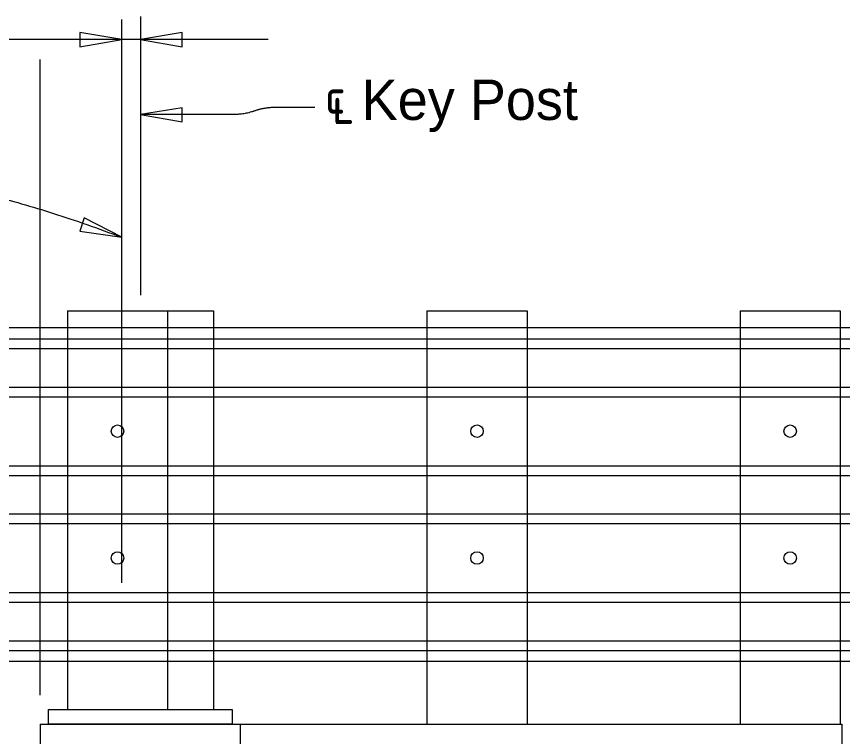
# Model space of a CAD drawing. Extents: x 21526.6 to 21598.7, y 56118.9 to 56155.9.
# Drawn here: x 21535.614 to 21539.735, y 56135.149 to 56138.742 of the extents above; entities that cross this region are included whole.
import ezdxf

# ---------------------------------------------------------------- set-up
doc = ezdxf.new("R2010")
doc.units = 0
for name, color, linetype in [('AdhocPoint_dp', 7, 'Continuous'), ('Border', 7, 'Continuous'), ('Patterning', 7, 'Continuous'), ('PlotBorder_dp', 7, 'Continuous'), ('SheetBorder_dp', 7, 'Continuous'), ('SubStrConc', 7, 'Continuous')]:
    doc.layers.add(name, color=color, linetype=linetype)

msp = doc.modelspace()

# ---------------------------------------------------------------- linework, layer by layer
at = {"layer": 'AdhocPoint_dp'}
for q in [(21535.7321, 56132.6054), (21536.7321, 56135.2101)]:
    msp.add_line((21535.7321, 56135.2101), q, dxfattribs=at)
at = {"layer": 'Patterning'}
for p, q in [((21536.2322, 56138.7421), (21536.2322, 56137.3509)), ((21536.1385, 56135.9162), (21536.1385, 56138.7274)), ((21535.8675, 56137.2726), (21536.5967, 56137.2726)), ((21535.8675, 56137.2726), (21535.8675, 56135.283)), ((21536.3675, 56137.2726), (21536.3675, 56135.283)), ((21537.6617, 56137.2725), (21537.6617, 56135.21)), ((21537.6617, 56137.2725), (21538.1617, 56137.2725)), ((21538.1617, 56137.2725), (21538.1617, 56135.21)), ((21539.2242, 56137.2725), (21539.2242, 56135.21)), ((21539.2242, 56137.2725), (21539.7242, 56137.2725)), ((21539.7242, 56137.2725), (21539.7242, 56135.21))]:
    msp.add_line(p, q, dxfattribs=at)
for centre in [(21536.1175, 56136.6725), (21536.1175, 56136.0393)]:
    msp.add_circle(centre, 0.0312, dxfattribs=at)
at = {"layer": 'PlotBorder_dp'}
for p, q in [((21536.8702, 56138.6267), (21533.9069, 56138.6267)), ((21535.7322, 56135.3555), (21535.7322, 56138.5276))]:
    msp.add_line(p, q, dxfattribs=at)
for points in [[(21536.1385, 56138.6267), (21535.9302, 56138.662), (21535.9302, 56138.5914)], [(21536.2322, 56138.6267), (21536.4405, 56138.5914), (21536.4405, 56138.662)], [(21536.2321, 56138.2534), (21536.44, 56138.2159), (21536.4408, 56138.2864)], [(21536.1385, 56137.6408), (21535.9508, 56137.7376), (21535.9294, 56137.6704)]]:
    msp.add_lwpolyline(points, close=True, dxfattribs=at)
for points in [[(21537.1016, 56138.2883), (21536.9673, 56138.2883), (21536.8507, 56138.2883), (21536.7517, 56138.253), (21536.6457, 56138.253), (21536.2321, 56138.2534)], [(21534.0219, 56137.913), (21534.2745, 56137.9191), (21535.2881, 56137.9608), (21536.1385, 56137.6408)]]:
    msp.add_open_spline(points, degree=2, dxfattribs=at)
at = {"layer": 'SheetBorder_dp'}
for p, q in [((21536.0134, 56137.2726), (21536.0967, 56137.2726)), ((21536.5967, 56137.2726), (21536.5967, 56135.283)), ((21541.6829, 56137.1892), (21534.1592, 56137.1892)), ((21534.1592, 56137.1336), (21541.6829, 56137.1336)), ((21534.1592, 56137.0854), (21541.6829, 56137.0854)), ((21534.1592, 56136.8926), (21541.6829, 56136.8926)), ((21534.1592, 56136.8444), (21541.6829, 56136.8444)), ((21534.1592, 56136.5004), (21541.6829, 56136.5004)), ((21534.1592, 56136.4522), (21541.6829, 56136.4522)), ((21534.1592, 56136.2594), (21541.6829, 56136.2594)), ((21534.1592, 56136.2112), (21541.6829, 56136.2112)), ((21534.1592, 56135.8673), (21541.6829, 56135.8673)), ((21534.1592, 56135.8191), (21541.6829, 56135.8191)), ((21534.1592, 56135.6262), (21541.6829, 56135.6262)), ((21534.1592, 56135.578), (21541.6829, 56135.578)), ((21541.6829, 56135.5225), (21534.1592, 56135.5225))]:
    msp.add_line(p, q, dxfattribs=at)
msp.add_lwpolyline([(21535.7738, 56135.2101), (21535.7738, 56135.283), (21536.6905, 56135.283), (21536.6905, 56135.2101)], close=True, dxfattribs=at)
for centre in [(21537.9117, 56136.6724), (21539.4742, 56136.6724), (21537.9117, 56136.0393), (21539.4742, 56136.0393)]:
    msp.add_circle(centre, 0.0312, dxfattribs=at)
at = {"layer": 'SubStrConc'}
for p, q in [((21536.7321, 56134.46), (21536.7321, 56135.2101)), ((21536.7321, 56135.2101), (21539.7321, 56135.2101)), ((21539.7321, 56135.2101), (21539.7321, 56134.46))]:
    msp.add_line(p, q, dxfattribs=at)

# ---------------------------------------------------------------- texts
at = {"layer": 'Border'}
msp.add_text('℄ Key Post', height=0.2016, dxfattribs=at).set_placement((21537.1518, 56138.2259))

doc.saveas('drawing.dxf')
